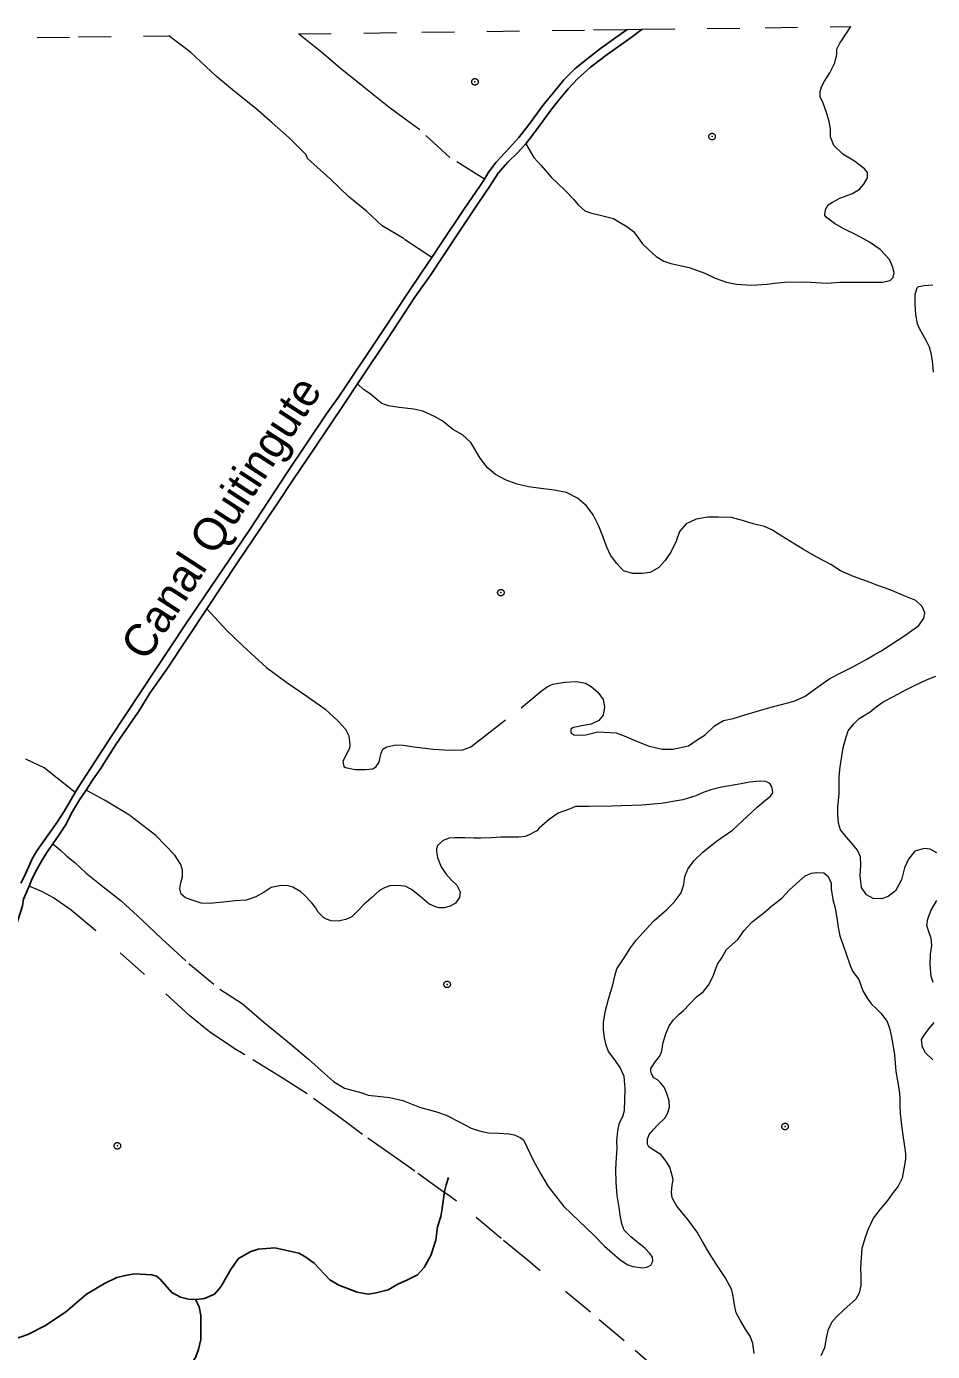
# Model space of a CAD drawing. Extents: x 267.7 to 296, y 7537.7 to 7565.8.
# Drawn here: x 285.983 to 288.764, y 7561.659 to 7565.725 of the extents above; entities that cross this region are included whole.
import ezdxf
from ezdxf.enums import TextEntityAlignment as Align

# ---------------------------------------------------------------- set-up
doc = ezdxf.new("R2010")
doc.units = 0
doc.header["$LTSCALE"] = 0.04
doc.header["$PDMODE"] = 32
doc.header["$PDSIZE"] = 0.02
doc.linetypes.add('SHORT_DASHED', pattern=[2.7, 1.5, -1.2])
for name, color, linetype, lineweight in [('1', 7, 'Continuous', 25), ('21', 7, 'SHORT_DASHED', 13), ('62', 7, 'SHORT_DASHED', 13), ('7', 7, 'Continuous', 25)]:
    doc.layers.add(name, color=color, linetype=linetype, lineweight=lineweight)

msp = doc.modelspace()

# ---------------------------------------------------------------- linework, layer by layer
at = {"layer": '1'}
for points in [[(287.8266, 7565.7158), (287.7849, 7565.686), (287.745, 7565.6573), (287.7128, 7565.6321), (287.6676, 7565.5956), (287.6329, 7565.5618), (287.6024, 7565.5235), (287.5686, 7565.4827), (287.5242, 7565.4218), (287.4947, 7565.3845), (287.4652, 7565.3515), (287.4243, 7565.308), (287.4008, 7565.2759), (287.3887, 7565.2567)], [(287.873, 7565.7164), (287.8394, 7565.6916), (287.7662, 7565.6394), (287.7145, 7565.5997), (287.6743, 7565.5639), (287.6457, 7565.5342), (287.6209, 7565.5034), (287.5956, 7565.4726), (287.5686, 7565.4346), (287.54, 7565.3961), (287.5163, 7565.3652)], [(287.5163, 7565.3652), (287.4905, 7565.3377), (287.4607, 7565.3091), (287.431, 7565.275), (287.4057, 7565.2353), (287.3683, 7565.1808), (287.3077, 7565.0884), (287.2631, 7565.0223), (287.2213, 7564.9584), (287.175, 7564.894), (287.0925, 7564.768), (287.0072, 7564.6403), (286.9989, 7564.6279)], [(287.3887, 7565.2567), (287.3765, 7565.2376), (287.3261, 7565.1629), (287.2575, 7565.0612), (287.2271, 7565.016)], [(287.2271, 7565.016), (287.1966, 7564.9709), (287.1506, 7564.9022), (287.0828, 7564.8005), (286.9429, 7564.5902), (286.9047, 7564.5364), (286.783, 7564.3565), (286.6666, 7564.1784), (286.4702, 7563.889), (286.2425, 7563.544), (286.1417, 7563.3893), (286.1332, 7563.3747)], [(286.9989, 7564.6279), (286.9615, 7564.5715), (286.8657, 7564.4284), (286.8024, 7564.3359), (286.7528, 7564.2605), (286.6306, 7564.0805), (286.5365, 7563.9379)], [(286.5365, 7563.9379), (286.4143, 7563.753), (286.362, 7563.6792), (286.3279, 7563.6241), (286.258, 7563.5212), (286.2107, 7563.4469), (286.1864, 7563.4122), (286.1661, 7563.3819)], [(286.1332, 7563.3747), (286.1, 7563.3181), (286.0774, 7563.2833), (286.0548, 7563.2512), (286.0322, 7563.2199), (286.0148, 7563.1955), (286.0009, 7563.1703), (285.9905, 7563.1469), (285.9756, 7563.1139), (285.9657, 7563.0964)], [(286.1661, 7563.3819), (286.1457, 7563.3517), (286.1248, 7563.3164), (286.1033, 7563.2735), (286.0824, 7563.2432), (286.064, 7563.2168)], [(286.064, 7563.2168), (286.0455, 7563.1904), (286.029, 7563.164), (286.0152, 7563.1375), (286.0009, 7563.1106), (285.9911, 7563.087)], [(285.9911, 7563.087), (285.9863, 7563.0752), (285.985, 7563.072), (285.9745, 7563.0467), (285.9707, 7563.0269), (285.9464, 7562.9487), (285.9206, 7562.8574), (285.898, 7562.7671), (285.8859, 7562.7346), (285.8551, 7562.6218), (285.8204, 7562.4974), (285.8011, 7562.4363), (285.7604, 7562.297), (285.7263, 7562.1699), (285.7119, 7562.1192), (285.6641, 7561.9535), (285.6349, 7561.8489), (285.625, 7561.8093), (285.6145, 7561.7727)]]:
    msp.add_lwpolyline(points, dxfattribs=at)
at = {"layer": '21'}
for points in [[(287.5163, 7565.3652), (287.5407, 7565.3225), (287.5634, 7565.2984), (287.5942, 7565.2624), (287.6128, 7565.2437), (287.6382, 7565.221), (287.6623, 7565.1956), (287.677, 7565.1782), (287.697, 7565.1595), (287.7144, 7565.1529), (287.7437, 7565.1462), (287.7851, 7565.1355), (287.8038, 7565.1248), (287.8265, 7565.1115), (287.8466, 7565.0954), (287.8613, 7565.0767), (287.8733, 7565.0594), (287.8933, 7565.0393), (287.916, 7565.0193), (287.9401, 7565.0046), (287.9614, 7564.9979), (288.0175, 7564.9859), (288.0656, 7564.9685), (288.0977, 7564.9525), (288.1324, 7564.9405), (288.1631, 7564.9338), (288.2085, 7564.9311), (288.2566, 7564.9338), (288.2793, 7564.9378), (288.31, 7564.9405), (288.3742, 7564.9418), (288.4396, 7564.9378), (288.4797, 7564.9405), (288.5197, 7564.9405), (288.5705, 7564.9405), (288.6106, 7564.9405), (288.6346, 7564.9458), (288.644, 7564.9552), (288.6466, 7564.9699), (288.6413, 7564.9886), (288.6319, 7565.0099), (288.6039, 7565.0407), (288.5705, 7565.0634), (288.5304, 7565.0861), (288.4944, 7565.1034), (288.4636, 7565.1208), (288.4383, 7565.1395), (288.4343, 7565.1462), (288.4356, 7565.1635), (288.4436, 7565.1782), (288.457, 7565.1862), (288.4797, 7565.1983), (288.5184, 7565.213), (288.5398, 7565.2263), (288.5531, 7565.241), (288.5652, 7565.261), (288.5652, 7565.2771), (288.5558, 7565.2878), (288.5251, 7565.3118), (288.489, 7565.3332), (288.461, 7565.3599), (288.4516, 7565.3866), (288.4516, 7565.4106), (288.4476, 7565.4333), (288.4383, 7565.4641), (288.4289, 7565.4894), (288.4196, 7565.5095), (288.4196, 7565.5255), (288.4236, 7565.5402), (288.4329, 7565.5576), (288.449, 7565.5829), (288.465, 7565.6136), (288.4703, 7565.639), (288.4703, 7565.6551), (288.4797, 7565.6738), (288.489, 7565.6871), (288.4984, 7565.7018), (288.5138, 7565.725)], [(287.2271, 7565.016), (287.1422, 7565.0731), (287.0748, 7565.1136), (287.0267, 7565.1579), (286.9728, 7565.2021), (286.915, 7565.258), (286.8457, 7565.3196), (286.8418, 7565.3311), (286.7898, 7565.3831), (286.7379, 7565.4293), (286.6878, 7565.4736), (286.6223, 7565.5256), (286.5665, 7565.5718), (286.5338, 7565.6026), (286.4876, 7565.645), (286.4202, 7565.6967)], [(287.3887, 7565.2567), (287.2828, 7565.3234), (287.1903, 7565.4082), (287.1422, 7565.4428), (287.096, 7565.4775), (287.019, 7565.5391), (286.9458, 7565.5969), (286.89, 7565.645), (286.8187, 7565.7021)], [(288.7671, 7564.6644), (288.7638, 7564.6988), (288.7605, 7564.7221), (288.7549, 7564.7409), (288.7449, 7564.7609), (288.7239, 7564.7985), (288.7183, 7564.8129), (288.7128, 7564.8407), (288.7106, 7564.8728), (288.7106, 7564.9038), (288.7172, 7564.9227), (288.7217, 7564.9271), (288.7383, 7564.9304), (288.7649, 7564.9326)], [(288.1814, 7564.2093), (288.1471, 7564.2178), (288.1076, 7564.2196), (288.075, 7564.2196), (288.0389, 7564.2127), (288.008, 7564.199), (287.9874, 7564.1749), (287.9771, 7564.1457), (287.9616, 7564.1114), (287.9428, 7564.0857), (287.9239, 7564.0651), (287.8981, 7564.0496), (287.8741, 7564.0462), (287.8432, 7564.0462), (287.8157, 7564.0547), (287.7951, 7564.0771), (287.7762, 7564.1028), (287.7642, 7564.1269), (287.7539, 7564.1578), (287.7402, 7564.1921), (287.723, 7564.2264), (287.7024, 7564.2539), (287.675, 7564.2779), (287.6406, 7564.2951), (287.6028, 7564.302), (287.5616, 7564.3071), (287.5239, 7564.3123), (287.4895, 7564.3208), (287.4552, 7564.3329), (287.4226, 7564.35), (287.3986, 7564.3706), (287.3762, 7564.3998), (287.3471, 7564.4479), (287.3213, 7564.4719), (287.2938, 7564.4874), (287.2595, 7564.5148), (287.2355, 7564.5286), (287.1994, 7564.544), (287.1719, 7564.5509), (287.1273, 7564.556), (287.0947, 7564.5612), (287.0741, 7564.5681), (287.0586, 7564.5801), (287.038, 7564.5972), (287.0174, 7564.611), (286.9989, 7564.6279)], [(288.3685, 7564.12), (288.3016, 7564.1612), (288.2707, 7564.1801), (288.2483, 7564.1904), (288.214, 7564.199), (288.1814, 7564.2093)], [(286.5365, 7563.9379), (286.5986, 7563.8711), (286.6483, 7563.823), (286.7204, 7563.7578), (286.7822, 7563.7114), (286.844, 7563.6702), (286.899, 7563.6307), (286.9402, 7563.5929), (286.9625, 7563.5689), (286.9728, 7563.5483), (286.9762, 7563.5208), (286.9745, 7563.5088), (286.9625, 7563.4865), (286.9539, 7563.4693), (286.9574, 7563.4539), (286.9625, 7563.4505), (286.9917, 7563.4453), (287.0243, 7563.4453), (287.0466, 7563.447), (287.0569, 7563.4539), (287.0655, 7563.4676), (287.0689, 7563.4831), (287.0724, 7563.4951), (287.0775, 7563.5071), (287.0895, 7563.514), (287.117, 7563.5208), (287.1393, 7563.5191), (287.1737, 7563.514), (287.232, 7563.5071), (287.2835, 7563.5037), (287.323, 7563.5054), (287.3471, 7563.514), (287.3745, 7563.5363), (287.5016, 7563.6341), (287.5634, 7563.6857), (287.5822, 7563.6994), (287.5994, 7563.7063), (287.6355, 7563.7131), (287.6715, 7563.7148), (287.699, 7563.7097), (287.7162, 7563.6994), (287.7368, 7563.6822), (287.7539, 7563.6599), (287.7574, 7563.6376), (287.7539, 7563.6118), (287.7402, 7563.5947), (287.7162, 7563.5844), (287.687, 7563.5792), (287.6732, 7563.5758), (287.6612, 7563.5741), (287.6544, 7563.5689), (287.6544, 7563.5569), (287.6629, 7563.5517), (287.675, 7563.55), (287.7007, 7563.5517), (287.7368, 7563.5603), (287.7934, 7563.5569), (287.8174, 7563.5483), (287.8535, 7563.5329), (287.8913, 7563.5174), (287.9342, 7563.5071), (287.9668, 7563.5071), (288.0149, 7563.5174), (288.0423, 7563.5363), (288.0664, 7563.5517), (288.0956, 7563.5792), (288.123, 7563.5947), (288.1522, 7563.6015), (288.1848, 7563.6118), (288.2329, 7563.6256), (288.2689, 7563.6359), (288.3393, 7563.6547), (288.3737, 7563.6702), (288.4046, 7563.6925), (288.4458, 7563.7217), (288.4767, 7563.7389), (288.5196, 7563.7595), (288.5625, 7563.7835), (288.5848, 7563.7972), (288.6054, 7563.8075), (288.6792, 7563.8556), (288.7222, 7563.8865), (288.7376, 7563.9088), (288.741, 7563.926), (288.7325, 7563.9449), (288.7136, 7563.9638), (288.6827, 7563.9758), (288.6346, 7563.9964), (288.5934, 7564.0101), (288.5728, 7564.0187), (288.5213, 7564.0376), (288.4818, 7564.0547), (288.4526, 7564.0736), (288.4097, 7564.096), (288.3685, 7564.12)], [(288.7774, 7563.1888), (288.7574, 7563.2006), (288.7385, 7563.2029), (288.7103, 7563.1947), (288.6903, 7563.17), (288.6785, 7563.1429), (288.6691, 7563.1064), (288.6503, 7563.0723), (288.6279, 7563.0547), (288.6079, 7563.0476), (288.582, 7563.0488), (288.562, 7563.0605), (288.5467, 7563.0829), (288.542, 7563.1182), (288.5444, 7563.1511), (288.5432, 7563.177), (288.5338, 7563.197), (288.5138, 7563.2217), (288.495, 7563.2429), (288.482, 7563.2594), (288.4761, 7563.2806), (288.4738, 7563.3065), (288.4738, 7563.3288), (288.4773, 7563.3712), (288.4773, 7563.4229), (288.4809, 7563.4535), (288.4856, 7563.4853), (288.4903, 7563.5112), (288.4985, 7563.5406), (288.5056, 7563.563), (288.5232, 7563.5853), (288.5397, 7563.6018), (288.5726, 7563.6218), (288.5915, 7563.6371), (288.6126, 7563.6524), (288.6444, 7563.6689), (288.6821, 7563.6889), (288.7091, 7563.703), (288.7456, 7563.7195), (288.775, 7563.7312)], [(286.1332, 7563.3747), (286.0774, 7563.4187), (286.0377, 7563.4503), (285.981, 7563.4762)], [(288.2532, 7563.3518), (288.2669, 7563.3634), (288.2743, 7563.3729), (288.2732, 7563.3823), (288.2711, 7563.3918), (288.2648, 7563.4023), (288.2532, 7563.4076), (288.2353, 7563.4086), (288.2027, 7563.4055), (288.1774, 7563.4013), (288.1164, 7563.3907), (288.0838, 7563.3823), (288.0606, 7563.3739), (288.0375, 7563.3644), (287.9975, 7563.3518), (287.9312, 7563.3402), (287.8723, 7563.335), (287.7786, 7563.3318), (287.7092, 7563.3308), (287.6682, 7563.3308), (287.6471, 7563.3223), (287.6155, 7563.3108), (287.5882, 7563.2929), (287.5566, 7563.2645), (287.5503, 7563.2561), (287.5261, 7563.2445), (287.5145, 7563.2392), (287.4945, 7563.2371), (287.4714, 7563.2371), (287.4398, 7563.2371), (287.4104, 7563.235), (287.3777, 7563.234), (287.3577, 7563.234), (287.3283, 7563.235), (287.2978, 7563.235), (287.2809, 7563.234), (287.262, 7563.2266), (287.2452, 7563.2119), (287.242, 7563.2013), (287.242, 7563.1929), (287.2452, 7563.175), (287.2557, 7563.1466), (287.2704, 7563.1245), (287.2883, 7563.1056), (287.3041, 7563.0898), (287.3146, 7563.0698), (287.3125, 7563.0519), (287.2999, 7563.0351), (287.2841, 7563.0256), (287.2662, 7563.0203), (287.2504, 7563.0203), (287.2388, 7563.0235), (287.2178, 7563.033), (287.1894, 7563.0572), (287.1652, 7563.0761), (287.1473, 7563.0856), (287.1262, 7563.0887), (287.0978, 7563.0877), (287.0799, 7563.0803), (287.0673, 7563.073), (287.041, 7563.0498), (287.02, 7563.0319), (286.9989, 7563.0098), (286.9821, 7562.993), (286.9631, 7562.9846), (286.94, 7562.9793), (286.919, 7562.9804), (286.9042, 7562.9856), (286.8958, 7562.9898), (286.879, 7563.0067), (286.8705, 7563.0214), (286.859, 7563.0361), (286.8358, 7563.0603), (286.8253, 7563.0698), (286.8011, 7563.0835), (286.7864, 7563.0877), (286.7653, 7563.0887), (286.7348, 7563.0824), (286.7127, 7563.0688), (286.6875, 7563.054), (286.658, 7563.0435), (286.6243, 7563.0414), (286.5875, 7563.0382), (286.5454, 7563.034), (286.5191, 7563.0351), (286.4917, 7563.0435), (286.4717, 7563.0509), (286.4581, 7563.0624), (286.4539, 7563.0782), (286.457, 7563.0972), (286.4623, 7563.115), (286.4623, 7563.1361), (286.457, 7563.1529), (286.4391, 7563.1824), (286.3802, 7563.2424)], [(286.3802, 7563.2424), (286.2992, 7563.3045), (286.2224, 7563.3508), (286.1661, 7563.3819)], [(288.0596, 7563.1908), (288.1017, 7563.2245), (288.1501, 7563.2582), (288.1806, 7563.2876), (288.2258, 7563.3297), (288.2532, 7563.3518)], [(286.064, 7563.2168), (286.0877, 7563.1975), (286.1073, 7563.1787), (286.1313, 7563.1598), (286.1664, 7563.1264), (286.2178, 7563.0862), (286.2743, 7563.0417), (286.3376, 7562.9835), (286.3984, 7562.9252), (286.4815, 7562.849), (286.5765, 7562.7711), (286.645, 7562.7266), (286.7118, 7562.6693), (286.7845, 7562.6102), (286.8488, 7562.5554), (286.8976, 7562.5117), (286.9258, 7562.4869), (286.9592, 7562.4664), (287.0123, 7562.4527), (287.032, 7562.4458), (287.0987, 7562.4381), (287.139, 7562.4295), (287.1895, 7562.4081), (287.2383, 7562.3953), (287.2717, 7562.3842), (287.3153, 7562.3611), (287.3479, 7562.3439), (287.377, 7562.3345), (287.401, 7562.3302), (287.4343, 7562.3285), (287.4635, 7562.3268), (287.4806, 7562.3234), (287.4986, 7562.3157), (287.5088, 7562.308), (287.5388, 7562.2455), (287.561, 7562.2052), (287.5842, 7562.165), (287.633, 7562.1042), (287.6783, 7562.0597), (287.7246, 7562.016), (287.758, 7561.9818), (287.805, 7561.9415), (287.8273, 7561.9261), (287.8444, 7561.9201), (287.8744, 7561.9155), (287.887, 7561.9176), (287.8997, 7561.9239), (287.906, 7561.9355), (287.9049, 7561.9481), (287.8975, 7561.9586), (287.8818, 7561.9755), (287.8555, 7561.9965), (287.8386, 7562.0102), (287.8176, 7562.0312), (287.8113, 7562.047), (287.8071, 7562.0712), (287.8028, 7562.1007), (287.7965, 7562.1375), (287.7934, 7562.1775), (287.7923, 7562.2185), (287.7944, 7562.2543), (287.7965, 7562.2817), (287.7955, 7562.3048), (287.7986, 7562.3364), (287.8039, 7562.3606), (287.8134, 7562.3795), (287.8186, 7562.3985), (287.8197, 7562.43), (287.8207, 7562.4658), (287.8176, 7562.5026), (287.806, 7562.53), (287.7892, 7562.5542), (287.7702, 7562.5795), (287.7629, 7562.5984), (287.7576, 7562.6215), (287.7544, 7562.6468), (287.7544, 7562.6699), (287.7608, 7562.7057), (287.7702, 7562.7404), (287.7829, 7562.7836), (287.7892, 7562.8109), (287.7955, 7562.833), (287.8197, 7562.8699), (287.8376, 7562.8972), (287.8555, 7562.9225), (287.8849, 7562.9551), (287.9091, 7562.9804), (287.9481, 7563.014), (287.9712, 7563.0382), (287.9933, 7563.0666), (288.0007, 7563.0919), (288.0038, 7563.1161), (288.0133, 7563.1393), (288.0312, 7563.1645), (288.0596, 7563.1908)], [(288.217, 7561.6526), (288.2132, 7561.6829), (288.2044, 7561.7057), (288.1905, 7561.7271), (288.1741, 7561.7549), (288.1615, 7561.7776), (288.1564, 7561.8016), (288.1526, 7561.8281), (288.1488, 7561.8483), (288.1274, 7561.8862), (288.0996, 7561.9292), (288.0794, 7561.9595), (288.0579, 7561.9961), (288.0415, 7562.0251), (288.0137, 7562.0643), (287.9796, 7562.1047), (287.9657, 7562.1299), (287.9632, 7562.1476), (287.9657, 7562.1691), (287.9683, 7562.1868), (287.9632, 7562.2057), (287.9582, 7562.2246), (287.9455, 7562.2436), (287.9304, 7562.2638), (287.9102, 7562.2751), (287.8938, 7562.2865), (287.89, 7562.2953), (287.89, 7562.3105), (287.895, 7562.3244), (287.9089, 7562.3408), (287.9215, 7562.3547), (287.943, 7562.3749), (287.9506, 7562.3888), (287.9569, 7562.409), (287.9556, 7562.4279), (287.9493, 7562.4507), (287.9405, 7562.4696), (287.9291, 7562.4835), (287.9203, 7562.4923), (287.9089, 7562.4986), (287.9013, 7562.5113), (287.9001, 7562.5188), (287.9001, 7562.5277), (287.914, 7562.5491), (287.9266, 7562.5643), (287.9329, 7562.5769), (287.9342, 7562.5883), (287.938, 7562.6072), (287.9455, 7562.6337), (287.9556, 7562.6577), (287.9695, 7562.6767), (287.9872, 7562.6944), (287.9998, 7562.7057), (288.02, 7562.7272), (288.0402, 7562.7474), (288.0604, 7562.7625), (288.0769, 7562.7827), (288.0907, 7562.8105), (288.0971, 7562.8282), (288.1046, 7562.8471), (288.1173, 7562.8673), (288.1324, 7562.8926), (288.1665, 7562.9229), (288.1854, 7562.9494), (288.2107, 7562.9772), (288.2461, 7563.005), (288.2713, 7563.0264), (288.3016, 7563.0504), (288.3256, 7563.0757), (288.3559, 7563.1035), (288.3736, 7563.1186), (288.3925, 7563.1262), (288.4089, 7563.1287), (288.4304, 7563.1275), (288.4443, 7563.1161), (288.4531, 7563.0959), (288.4531, 7563.0782), (288.4582, 7563.0454), (288.4658, 7563.0189), (288.4708, 7562.9898), (288.4746, 7562.9595), (288.4797, 7562.9343), (288.491, 7562.9027), (288.4986, 7562.8825), (288.5112, 7562.8434), (288.5188, 7562.8257), (288.5377, 7562.8004), (288.5504, 7562.7651)], [(287.2656, 7562.1471), (287.1753, 7562.2118), (287.1125, 7562.2561), (287.0142, 7562.3251), (286.9452, 7562.3765), (286.8452, 7562.449), (286.7629, 7562.5012), (286.6532, 7562.5687), (286.6204, 7562.5889), (286.6071, 7562.5977), (286.5451, 7562.6402), (286.485, 7562.6889), (286.3451, 7562.8154), (286.1956, 7562.9508), (286.1203, 7563.0128), (286.0663, 7563.0509), (286.0327, 7563.0694), (285.9911, 7563.087)], [(288.7668, 7562.7911), (288.7597, 7562.8111), (288.7574, 7562.8452), (288.7585, 7562.8782), (288.7621, 7562.9052), (288.7597, 7562.9276), (288.7538, 7562.944), (288.7468, 7562.9664), (288.7503, 7562.9864), (288.7597, 7563.0135), (288.7774, 7563.0429)], [(288.5504, 7562.7651), (288.5655, 7562.7398), (288.5781, 7562.7234), (288.5895, 7562.7133), (288.6059, 7562.6969), (288.6249, 7562.6716)], [(288.6249, 7562.6716), (288.6324, 7562.6514), (288.6375, 7562.6287), (288.6425, 7562.6009), (288.6476, 7562.5694)], [(288.7656, 7562.5534), (288.7432, 7562.5758), (288.7338, 7562.5922), (288.7303, 7562.6158), (288.7362, 7562.6263), (288.7503, 7562.6452), (288.7691, 7562.6687)], [(288.6476, 7562.5694), (288.6514, 7562.5176), (288.6564, 7562.4898), (288.6615, 7562.4595), (288.664, 7562.4368), (288.664, 7562.4166), (288.6653, 7562.3888), (288.6691, 7562.3522), (288.6741, 7562.3155), (288.6792, 7562.2815), (288.6817, 7562.265), (288.6817, 7562.2486), (288.6766, 7562.2196), (288.6716, 7562.1905), (288.659, 7562.1665), (288.6438, 7562.1463), (288.6261, 7562.1224), (288.6034, 7562.0958), (288.5832, 7562.0693), (288.5668, 7562.034), (288.5579, 7562.0087), (288.5478, 7561.9746), (288.5453, 7561.9468), (288.5428, 7561.9153), (288.5441, 7561.8913), (288.5441, 7561.861), (288.539, 7561.8382), (288.5289, 7561.8193), (288.5112, 7561.8042), (288.4923, 7561.7865), (288.4696, 7561.765), (288.4544, 7561.7473), (288.443, 7561.7233), (288.4392, 7561.7044), (288.4329, 7561.6703), (288.4216, 7561.6451)], [(287.9267, 7561.5959), (287.8178, 7561.6914), (287.7143, 7561.7791), (287.5532, 7561.9127), (287.5249, 7561.9357), (287.4399, 7562.0056), (287.3036, 7562.1198), (287.2753, 7562.1402), (287.2656, 7562.1471)]]:
    msp.add_lwpolyline(points, dxfattribs=at)
for p in [(287.3599, 7565.5552), (288.0877, 7565.3872), (287.4395, 7563.9876), (287.2745, 7562.7854), (288.3117, 7562.3493), (286.2622, 7562.2899)]:
    msp.add_point(p, dxfattribs=at)
at = {"layer": '62'}
msp.add_line((287.8266, 7565.7158), (287.873, 7565.7164), dxfattribs=at)
for points in [[(286.8187, 7565.7021), (287.1966, 7565.7073), (287.7235, 7565.7144), (287.8266, 7565.7158)], [(287.873, 7565.7164), (288.2504, 7565.7214), (288.5138, 7565.725)], [(284.3271, 7565.6683), (284.562, 7565.6715), (285.0889, 7565.6787), (285.6159, 7565.6859), (286.1428, 7565.693), (286.4202, 7565.6967)]]:
    msp.add_lwpolyline(points, dxfattribs=at)
at = {"layer": '7'}
for points in [[(287.2791, 7562.1924), (287.271, 7562.1699), (287.2659, 7562.1494), (287.2656, 7562.1471)], [(287.2656, 7562.1471), (287.265, 7562.1424), (287.2597, 7562.0981), (287.2556, 7562.0735), (287.2453, 7562.0418), (287.2394, 7562.0005), (287.2248, 7561.9534), (287.2043, 7561.9164), (287.1835, 7561.8939), (287.153, 7561.8784), (287.1232, 7561.8651), (287.0938, 7561.8478), (287.0567, 7561.8386), (287.0319, 7561.8343), (286.998, 7561.8404), (286.9423, 7561.8621), (286.9145, 7561.8789), (286.8666, 7561.9298), (286.8379, 7561.9503), (286.8192, 7561.9606), (286.7451, 7561.977), (286.6942, 7561.973), (286.6721, 7561.9658), (286.6343, 7561.9439), (286.6114, 7561.9129), (286.5794, 7561.8574), (286.5606, 7561.8349), (286.5293, 7561.8217), (286.5043, 7561.8186), (286.5022, 7561.8188)], [(286.5022, 7561.8188), (286.4807, 7561.8189), (286.456, 7561.8251), (286.4294, 7561.8394), (286.3924, 7561.8815), (286.3821, 7561.8897), (286.3679, 7561.8943), (286.3144, 7561.8969), (286.291, 7561.8927), (286.261, 7561.8856), (286.223, 7561.8678), (286.1677, 7561.8351), (286.1035, 7561.7795), (286.0399, 7561.7377), (285.9876, 7561.7108), (285.9168, 7561.6859), (285.8915, 7561.6816), (285.786, 7561.6958), (285.7642, 7561.7039), (285.7143, 7561.7406), (285.6641, 7561.7725), (285.6376, 7561.7756), (285.6145, 7561.7727)], [(286.3735, 7561.5023), (286.3924, 7561.5305), (286.415, 7561.552), (286.4458, 7561.5767), (286.4909, 7561.6218), (286.5033, 7561.6424), (286.5115, 7561.6649), (286.5182, 7561.6952), (286.518, 7561.7695), (286.5136, 7561.7963), (286.5022, 7561.8188)]]:
    msp.add_lwpolyline(points, dxfattribs=at)

# ---------------------------------------------------------------- texts
at = {"layer": '1'}
msp.add_text('Canal Quitingute', height=0.1, rotation=57.006, dxfattribs=at).set_placement((286.6222, 7564.1909), align=Align.CENTER)

doc.saveas('drawing.dxf')
